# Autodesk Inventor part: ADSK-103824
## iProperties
Shininess: 27.0
Created: 2001-04
Part Number: ADSK-103824
Document SubType Name: Modeling
Designer: Administrator
Stock Number: ADSK-103824
Density: 1 g/cm^3
Density: 0.0
Volumn: 0.0
Area: 0.0
PropertySet Name: Model Information
Control State: 0
Master: False
Checked Out: False
Author: Administrator
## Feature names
1. Extrusion1
2. Extrusion2
3. Hole1
4. Chamfer1
